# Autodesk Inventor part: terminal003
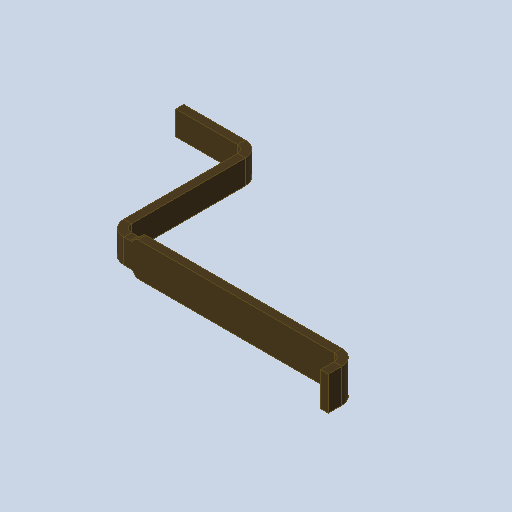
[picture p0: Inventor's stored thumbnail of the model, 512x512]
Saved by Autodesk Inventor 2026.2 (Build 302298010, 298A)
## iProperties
Created: 2026-10
Part Number: terminal003
Material: Générique
Document SubType Name: Modeling
Designer: mel
Density: 1 g/cm^3
Appearance: Par défaut
Author: mel
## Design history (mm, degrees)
feature "Base1"
node "Solide1"
